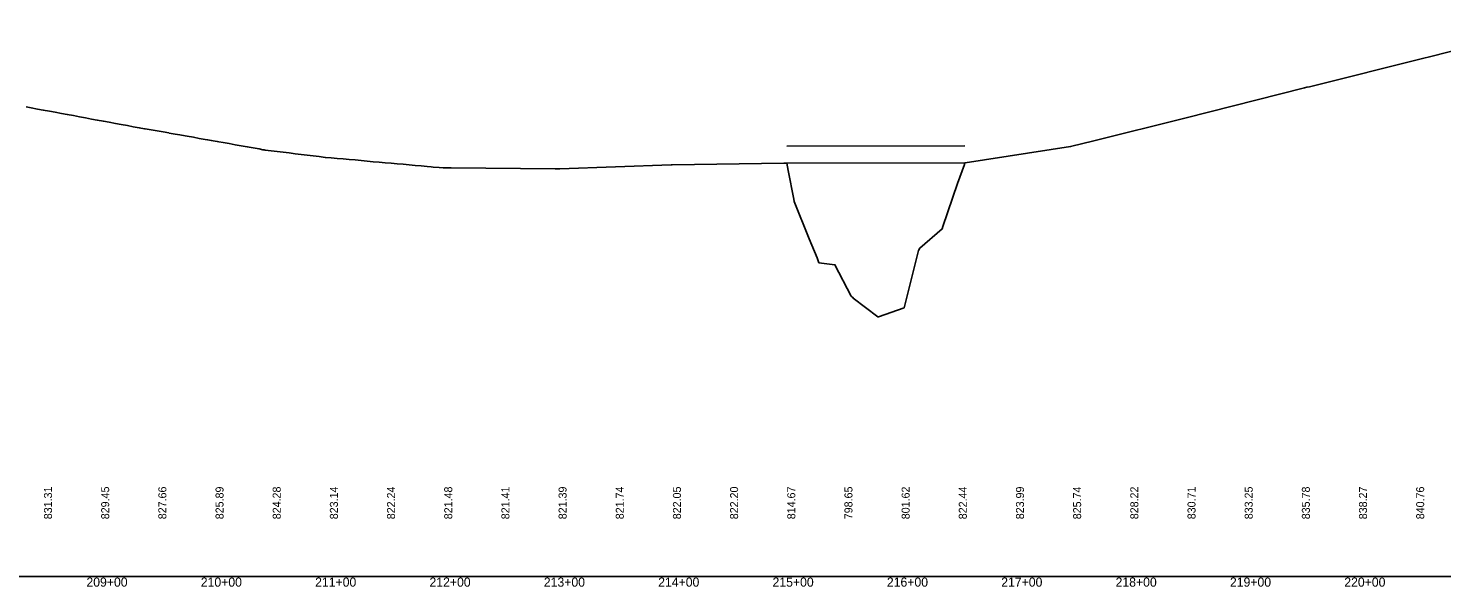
# Model space of a CAD drawing. Extents: x 1475855 to 1480900, y 1104511 to 1111511.
# Drawn here: x 1478436 to 1479672, y 1110502 to 1110991 of the extents above; entities that cross this region are included whole.
import ezdxf

# ---------------------------------------------------------------- set-up
doc = ezdxf.new("R2010")
doc.units = 0
for name, color, linetype in [('Default', 7, 'Continuous'), ('RD_DDB_Profile_EX', 7, 'Continuous'), ('RD_DDB_StaTX', 7, 'Continuous'), ('RD_DDB_StripGrade', 7, 'Continuous'), ('RD_GPK_Profile_Cell', 7, 'Continuous')]:
    doc.layers.add(name, color=color, linetype=linetype)

msp = doc.modelspace()

# ---------------------------------------------------------------- linework, layer by layer
at = {"layer": 'Default'}
for p, q in [((1479099.1, 1110887.9), (1479254.8, 1110888.1)), ((1479099.1, 1110872.9), (1479254.8, 1110873.1))]:
    msp.add_line(p, q, dxfattribs=at)
at = {"layer": 'RD_DDB_Profile_EX'}
msp.add_lwpolyline([(1478433.9, 1110922.2), (1478438.4, 1110921.3), (1478443.7, 1110920.3), (1478448.9, 1110919.4), (1478454.2, 1110918.4), (1478459.4, 1110917.4), (1478464.7, 1110916.4), (1478469.9, 1110915.5), (1478475.2, 1110914.5), (1478480.4, 1110913.5), (1478485.9, 1110912.5), (1478488.4, 1110912), (1478490.9, 1110911.5), (1478496.1, 1110910.6), (1478501.4, 1110909.6), (1478506.6, 1110908.7), (1478511.9, 1110907.7), (1478517.1, 1110906.7), (1478522.4, 1110905.8), (1478527.6, 1110904.8), (1478532.8, 1110903.9), (1478537.3, 1110903), (1478537.7, 1110903), (1478538.1, 1110902.9), (1478543.3, 1110902), (1478548.6, 1110901.1), (1478553.8, 1110900.2), (1478558.6, 1110899.3), (1478559.1, 1110899.2), (1478564.3, 1110898.3), (1478568.4, 1110897.6), (1478569.6, 1110897.4), (1478574.8, 1110896.5), (1478580.1, 1110895.6), (1478585.3, 1110894.6), (1478590.5, 1110893.7), (1478592.4, 1110893.4), (1478592.9, 1110893.3), (1478595.8, 1110892.8), (1478601, 1110891.9), (1478602.4, 1110891.6), (1478606.3, 1110890.9), (1478611.5, 1110890), (1478616.8, 1110889), (1478622, 1110888.1), (1478627.3, 1110887.2), (1478632.5, 1110886.2), (1478637.8, 1110885.3), (1478641, 1110884.7), (1478641.9, 1110884.5), (1478643, 1110884.4), (1478648.2, 1110883.8), (1478653.5, 1110883.1), (1478658.7, 1110882.5), (1478664, 1110881.8), (1478669.2, 1110881.2), (1478674.5, 1110880.6), (1478679.7, 1110879.9), (1478685, 1110879.3), (1478690.2, 1110878.7), (1478691.9, 1110878.4), (1478695.4, 1110878), (1478695.8, 1110878), (1478700.7, 1110877.5), (1478705.9, 1110877.1), (1478711.2, 1110876.6), (1478716.4, 1110876.1), (1478721.7, 1110875.7), (1478726.9, 1110875.2), (1478732.2, 1110874.7), (1478737.4, 1110874.2), (1478742.7, 1110873.8), (1478747.9, 1110873.3), (1478753.1, 1110872.8), (1478758.4, 1110872.4), (1478763.6, 1110871.9), (1478768.9, 1110871.4), (1478774.1, 1110870.9), (1478779.4, 1110870.5), (1478784.6, 1110870), (1478788.1, 1110869.7), (1478789.9, 1110869.5), (1478795.1, 1110869), (1478798.6, 1110868.7), (1478800.3, 1110868.7), (1478805.6, 1110868.7), (1478896.6, 1110868), (1478900.6, 1110868), (1478998.1, 1110871.4), (1478998.7, 1110871.4), (1479096.6, 1110872.8), (1479099.1, 1110872.9), (1479100.3, 1110866.4), (1479105.1, 1110841.5), (1479105.6, 1110839.2), (1479118.6, 1110806.7), (1479125.7, 1110789.9), (1479127.1, 1110785.8), (1479141.2, 1110784), (1479155.3, 1110756.5), (1479156.1, 1110755.6), (1479156.8, 1110755.5), (1479157.2, 1110754.7), (1479178.8, 1110738.3), (1479179.3, 1110738.5), (1479201.7, 1110746.4), (1479214.3, 1110796.5), (1479215.3, 1110798.6), (1479234.9, 1110815.4), (1479235.5, 1110817.6), (1479248.5, 1110855.1), (1479254.4, 1110871.8), (1479254.8, 1110873.1), (1479255.2, 1110873.1), (1479347.2, 1110887.4), (1479367.6, 1110892.5), (1479447.1, 1110912.2), (1479551.9, 1110938.7), (1479554, 1110939.3), (1479556.1, 1110939.8), (1479657.4, 1110965.1), (1479660, 1110965.7), (1479760, 1110991)], dxfattribs=at)
at = {"layer": 'RD_GPK_Profile_Cell'}
msp.add_line((1477571, 1110511.2), (1480900.4, 1110511.2), dxfattribs=at)

# ---------------------------------------------------------------- texts
at = {"layer": 'RD_DDB_StaTX'}
for s, p in [('209+00', (1478486.6, 1110502.2)), ('210+00', (1478586.6, 1110502.2)), ('211+00', (1478686.6, 1110502.2)), ('212+00', (1478786.6, 1110502.2)), ('213+00', (1478886.6, 1110502.2)), ('214+00', (1478986.6, 1110502.2)), ('215+00', (1479086.6, 1110502.2)), ('216+00', (1479186.6, 1110502.2)), ('217+00', (1479286.6, 1110502.2)), ('218+00', (1479386.6, 1110502.2)), ('219+00', (1479486.6, 1110502.2)), ('220+00', (1479586.6, 1110502.2))]:
    msp.add_text(s, height=8, dxfattribs=at).set_placement(p)
at = {"layer": 'RD_DDB_StripGrade'}
for s, p in [('831.31', (1478456.5, 1110561.2)), ('829.45', (1478506.5, 1110561.2)), ('827.66', (1478556.5, 1110561.2)), ('825.89', (1478606.5, 1110561.2)), ('824.28', (1478656.5, 1110561.2)), ('823.14', (1478706.5, 1110561.2)), ('822.24', (1478756.5, 1110561.2)), ('821.48', (1478806.5, 1110561.2)), ('821.41', (1478856.5, 1110561.2)), ('821.39', (1478906.5, 1110561.2)), ('821.74', (1478956.5, 1110561.2)), ('822.05', (1479006.5, 1110561.2)), ('822.20', (1479056.5, 1110561.2)), ('814.67', (1479106.5, 1110561.2)), ('798.65', (1479156.5, 1110561.2)), ('801.62', (1479206.5, 1110561.2)), ('822.44', (1479256.5, 1110561.2)), ('823.99', (1479306.5, 1110561.2)), ('825.74', (1479356.5, 1110561.2)), ('828.22', (1479406.5, 1110561.2)), ('830.71', (1479456.5, 1110561.2)), ('833.25', (1479506.5, 1110561.2)), ('835.78', (1479556.5, 1110561.2)), ('838.27', (1479606.5, 1110561.2)), ('840.76', (1479656.5, 1110561.2))]:
    msp.add_text(s, height=7, rotation=90, dxfattribs=at).set_placement(p)

doc.saveas('drawing.dxf')
